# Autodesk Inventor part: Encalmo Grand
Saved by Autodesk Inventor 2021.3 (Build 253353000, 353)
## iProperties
Created: 2022-07
Part Number: Encalmo Grand
Material: Generic
Document SubType Name: Modeling
Designer: Administrator
Density: 1 g/cm^3
Appearance: Default
Title: Encalmo Grand v10
Author: Administrator
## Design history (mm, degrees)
feature "Encalmo Grand" [Body]
feature "Encalmo Grand (1)" [Body]
feature "Socket Body" [Body]
feature "Shade Ring" [Body]
feature "Shade Ring +Collar" [Body]
feature "Socket" [Body]
feature "Body1"
feature "Metal Strain Relief" [Body]
feature "Fabric Cord (1)" [Body]
feature "Stem (Threaded)" [Body]
feature "Cap (Threaded)" [Body]
feature "5M Set Screw" [Body]
feature "T9-Bulb" [Body]
body "Solid1"
body "Solid2"
body "Solid3"
body "Solid4"
body "Solid5"
body "Solid6"
body "Solid7"
body "Solid8"
body "Solid9"
body "Solid10"
body "Solid11"
body "Solid12"
body "Solid13"
